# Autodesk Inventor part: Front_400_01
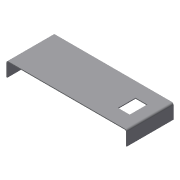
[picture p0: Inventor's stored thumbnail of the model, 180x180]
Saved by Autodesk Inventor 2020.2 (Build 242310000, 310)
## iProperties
Created: 2014-10
Part Number: Front_400_01
Material: Ogólny
Document SubType Name: Konstrukcja blachowa
Designer: F.Stasiak
Density: 1 g/cm^3
Sheet Metal Rule: Domyślny_mm
Appearance: Domyślna
Catalog Web Link: www.expertbooks.pl
Manager: www.cadconsulting.pl
Company: Fabian Stasiak CAD Consulting
Author: F.Stasiak
Subject: Zbiór ćwiczeń. Autodesk Inventor 2020. Kurs Professional
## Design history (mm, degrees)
node "Powierzchnia1"
  sketch "Szkic1"
    geometry: L1 (-100, 40)-(100, 40); L2 (100, 40)-(100, -40); L3 (100, -40)-(-100, -40); L4 (-100, -40)-(-100, 40); L5 (-100, 40)-(100, -40); L6 (100, 40)-(-100, -40); 1 further point
    constraints: 12 end point, 2 midpoint, 2 parallel, 1 horizontal, 1 perpendicular
    dimensions: "d0" = 200 distance of L2.end L3.end; "d1" = 80 distance of L1.end L2.end
node "Kołnierz1"
sketch "Szkic3"
  geometry: L1 (83, -15)-(63, -15); L2 (63, -15)-(63, 15); L3 (63, 15)-(83, 15); L4 (83, 15)-(83, -15); L5 (100, 40)-(100, -40) reference; L6 (103, 40)-(103, -40) reference; 3 further points
  constraints: 8 end point, 2 midpoint, 2 parallel, 1 horizontal, 1 horizontal alignment, 1 perpendicular
  dimensions: "d13" = 20 distance of L2.end L3.end; "d14" = 30 distance of L1.end L2.end; "d15" = 20 distance between parallel lines of L6 L4
feature "Wytnij1" sketch "Szkic3" dims "d16" = 1.5 (= Grubość), "d17" = 0
node "Bryła1"
feature "Płyta1" dims "d18" = 1.5 (= Grubość)
sketch "Szkic2"
  geometry: L1 (0, -22)-(80, -22); L2 (80, -22)-(80, 0); 1 other entity
  constraints: 4 end point, 4 other
feature "Płyta2" dims "d3" = 1.5 (= SzerokośćGięciaPodcięcia), "d4" = 0.75 (= GłębokośćGięciaPodcięcia), "d5" = 3 (= MinimalnaPozostałość), "d6" = 1.5 (= PromieńGięcia), "d7" = 25, "d8" = 90 deg, "d9" = 1.5 (= PromieńGięcia), "d10" = 6 (= RozmiarPodcięciaNarożnika), "d11" = 1.5 (= Wielk_odstępu), "d12" = 1.5 (= Rozmiar_promienia_Jacobiego), "d18" = 1.5 (= Grubość), "OdstępPołączenia" = 0.01
feature "Gięcie1" dims "d3" = 1.5 (= SzerokośćGięciaPodcięcia), "d4" = 0.75 (= GłębokośćGięciaPodcięcia), "d5" = 3 (= MinimalnaPozostałość), "d6" = 1.5 (= PromieńGięcia), "d7" = 25, "d8" = 90 deg, "d9" = 1.5 (= PromieńGięcia), "d18" = 1.5 (= Grubość), "OdstępPołączenia" = 0.01
feature "Narożnik1" dims "d7" = 25, "d8" = 90 deg, "d10" = 6 (= RozmiarPodcięciaNarożnika), "d11" = 1.5 (= Wielk_odstępu), "d12" = 1.5 (= Rozmiar_promienia_Jacobiego)
other parameters: "Grubość" = 1.5, "WspółczynnikK" = 4.4, "PromieńGięcia" = 1.5 (= Grubość), "SzerokośćGięciaPodcięcia" = 1.5 (= Grubość), "GłębokośćGięciaPodcięcia" = 0.75 (= 0.5 x Grubość), "RozmiarPodcięciaNarożnika" = 6 (= 4 x Grubość), "MinimalnaPozostałość" = 3 (= 2 x Grubość), "PromieńPrzejścia" = 1.5 (= PromieńGięcia), "Rozmiar_promienia_Jacobiego" = 1.5 (= PromieńGięcia), "Wielk_odstępu" = 1.5 (= Grubość), "d2" = 1.5 (= PromieńGięcia)
